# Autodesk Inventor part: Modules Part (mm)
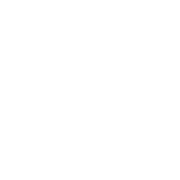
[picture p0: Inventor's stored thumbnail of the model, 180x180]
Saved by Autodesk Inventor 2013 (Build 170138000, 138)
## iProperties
Created: 2008-05
Part Number: Modules Part (mm)
Document SubType Name: Modeling
Designer: Wally
Density: 1 g/cm^3
Material: Generic
Author: Wally
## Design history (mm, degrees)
node "Sketch1"
